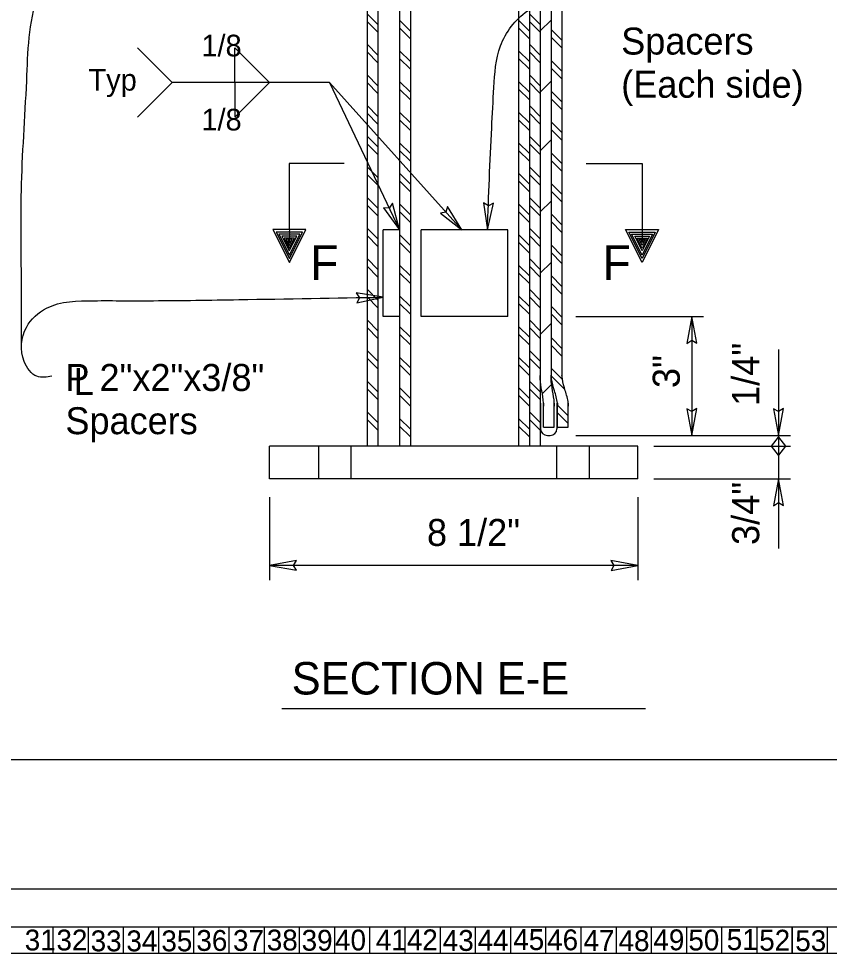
# Model space of a CAD drawing. Extents: x 0 to 2.83, y -0.03 to 1.83.
# Drawn here: x 0.6135 to 1.0034, y -0.0308 to 0.4189 of the extents above; entities that cross this region are included whole.
import ezdxf

# ---------------------------------------------------------------- set-up
doc = ezdxf.new("R2010")
doc.units = 0
for name, color, linetype in [('31', 7, 'Continuous'), ('32', 7, 'Continuous'), ('33', 7, 'Continuous'), ('34', 7, 'Continuous'), ('35', 7, 'Continuous'), ('36', 7, 'Continuous'), ('37', 7, 'Continuous'), ('38', 7, 'Continuous'), ('39', 7, 'Continuous'), ('40', 7, 'Continuous'), ('41', 7, 'Continuous'), ('42', 7, 'Continuous'), ('43', 7, 'Continuous'), ('44', 7, 'Continuous'), ('45', 7, 'Continuous'), ('46', 7, 'Continuous'), ('47', 7, 'Continuous'), ('48', 7, 'Continuous'), ('49', 7, 'Continuous'), ('50', 7, 'Continuous'), ('51', 7, 'Continuous'), ('52', 7, 'Continuous'), ('53', 7, 'Continuous'), ('54', 7, 'Continuous'), ('55', 7, 'Continuous'), ('57', 7, 'Continuous'), ('59', 7, 'Continuous'), ('62', 7, 'Continuous'), ('63', 7, 'Continuous')]:
    doc.layers.add(name, color=color, linetype=linetype)

msp = doc.modelspace()

# ---------------------------------------------------------------- linework, layer by layer
at = {"layer": '50'}
for p, q in [((0.86439, 0.41305), (0.8696, 0.41826)), ((0.86439, 0.38359), (0.8696, 0.3888)), ((0.86439, 0.35537), (0.8696, 0.36058)), ((0.86439, 0.32591), (0.8696, 0.33112)), ((0.86439, 0.29644), (0.8696, 0.30165)), ((0.86439, 0.26698), (0.8696, 0.27219)), ((0.86532, 0.23844), (0.86989, 0.24301))]:
    msp.add_line(p, q, dxfattribs=at)
at = {"layer": '52'}
for p, q in [((0.79669, 0.64876), (0.79669, 0.21316)), ((0.80189, 0.64876), (0.80189, 0.21316)), ((0.85398, 0.64876), (0.85398, 0.21316)), ((0.85919, 0.64876), (0.85919, 0.21316)), ((0.8696, 0.57644), (0.8696, 0.24567)), ((0.87481, 0.57644), (0.87481, 0.24743)), ((0.78106, 0.57253), (0.78106, 0.21316)), ((0.78627, 0.57253), (0.78627, 0.21316)), ((0.86439, 0.57253), (0.86439, 0.21316)), ((0.78627, 0.41611), (0.78106, 0.42132)), ((0.86439, 0.41611), (0.85919, 0.42132)), ((0.78627, 0.41243), (0.78106, 0.41763)), ((0.80189, 0.41297), (0.79669, 0.41818)), ((0.80189, 0.40928), (0.79669, 0.41449)), ((0.85919, 0.41297), (0.85398, 0.41818)), ((0.85919, 0.40928), (0.85398, 0.41449)), ((0.86439, 0.41243), (0.85919, 0.41763)), ((0.87481, 0.40853), (0.8696, 0.41373)), ((0.87481, 0.40484), (0.8696, 0.41005)), ((0.78627, 0.40138), (0.78106, 0.40659)), ((0.86439, 0.40138), (0.85919, 0.40659)), ((0.78627, 0.3977), (0.78106, 0.4029)), ((0.80189, 0.39824), (0.79669, 0.40344)), ((0.85919, 0.39824), (0.85398, 0.40344)), ((0.86439, 0.3977), (0.85919, 0.4029)), ((0.80189, 0.39455), (0.79669, 0.39976)), ((0.85919, 0.39455), (0.85398, 0.39976)), ((0.87481, 0.3936), (0.8696, 0.39881)), ((0.78627, 0.38665), (0.78106, 0.39185)), ((0.86439, 0.38665), (0.85919, 0.39185)), ((0.87481, 0.38992), (0.8696, 0.39512)), ((0.78627, 0.38296), (0.78106, 0.38817)), ((0.80189, 0.38351), (0.79669, 0.38871)), ((0.85919, 0.38351), (0.85398, 0.38871)), ((0.86439, 0.38296), (0.85919, 0.38817)), ((0.80189, 0.37982), (0.79669, 0.38503)), ((0.85919, 0.37982), (0.85398, 0.38503)), ((0.87481, 0.37887), (0.8696, 0.38408)), ((0.87481, 0.37519), (0.8696, 0.38039)), ((0.78627, 0.37192), (0.78106, 0.37712)), ((0.78627, 0.36823), (0.78106, 0.37344)), ((0.80189, 0.36877), (0.79669, 0.37398)), ((0.85919, 0.36877), (0.85398, 0.37398)), ((0.86439, 0.37192), (0.85919, 0.37712)), ((0.86439, 0.36823), (0.85919, 0.37344)), ((0.80189, 0.36509), (0.79669, 0.3703)), ((0.85919, 0.36509), (0.85398, 0.3703)), ((0.87481, 0.36414), (0.8696, 0.36934)), ((0.87481, 0.36045), (0.8696, 0.36566)), ((0.78627, 0.35718), (0.78106, 0.36239)), ((0.86439, 0.35718), (0.85919, 0.36239)), ((0.78627, 0.3535), (0.78106, 0.35871)), ((0.80189, 0.35404), (0.79669, 0.35925)), ((0.80189, 0.35036), (0.79669, 0.35557)), ((0.85919, 0.35404), (0.85398, 0.35925)), ((0.85919, 0.35036), (0.85398, 0.35557)), ((0.86439, 0.3535), (0.85919, 0.35871)), ((0.87481, 0.34921), (0.8696, 0.35442)), ((0.78627, 0.34245), (0.78106, 0.34766)), ((0.86439, 0.34245), (0.85919, 0.34766)), ((0.87481, 0.34553), (0.8696, 0.35074)), ((0.78627, 0.33877), (0.78106, 0.34398)), ((0.80189, 0.33931), (0.79669, 0.34452)), ((0.85919, 0.33931), (0.85398, 0.34452)), ((0.86439, 0.33877), (0.85919, 0.34398)), ((0.80189, 0.33563), (0.79669, 0.34084)), ((0.85919, 0.33563), (0.85398, 0.34084)), ((0.87481, 0.33448), (0.8696, 0.33969)), ((0.78627, 0.32772), (0.78106, 0.33293)), ((0.86439, 0.32772), (0.85919, 0.33293)), ((0.87481, 0.3308), (0.8696, 0.336)), ((0.78627, 0.32404), (0.78106, 0.32925)), ((0.80189, 0.32458), (0.79669, 0.32979)), ((0.85919, 0.32458), (0.85398, 0.32979)), ((0.86439, 0.32404), (0.85919, 0.32925)), ((0.80189, 0.3209), (0.79669, 0.3261)), ((0.85919, 0.3209), (0.85398, 0.3261)), ((0.87481, 0.31975), (0.8696, 0.32496)), ((0.87481, 0.31606), (0.8696, 0.32127)), ((0.78627, 0.31299), (0.78106, 0.3182)), ((0.79669, 0.31732), (0.78887, 0.31732)), ((0.78887, 0.27566), (0.78887, 0.31732)), ((0.80189, 0.30985), (0.79669, 0.31506)), ((0.8071, 0.27566), (0.8071, 0.31732)), ((0.84877, 0.31732), (0.8071, 0.31732)), ((0.84877, 0.27566), (0.84877, 0.31732)), ((0.85919, 0.30985), (0.85398, 0.31506)), ((0.86439, 0.31299), (0.85919, 0.3182)), ((0.78627, 0.30931), (0.78106, 0.31452)), ((0.80189, 0.30617), (0.79669, 0.31137)), ((0.85919, 0.30617), (0.85398, 0.31137)), ((0.86439, 0.30931), (0.85919, 0.31452)), ((0.87481, 0.30482), (0.8696, 0.31003)), ((0.87481, 0.30114), (0.8696, 0.30635)), ((0.78627, 0.29826), (0.78106, 0.30347)), ((0.86439, 0.29826), (0.85919, 0.30347)), ((0.78627, 0.29458), (0.78106, 0.29978)), ((0.80189, 0.29512), (0.79669, 0.30033)), ((0.85919, 0.29512), (0.85398, 0.30033)), ((0.86439, 0.29458), (0.85919, 0.29978)), ((0.80189, 0.29143), (0.79669, 0.29664)), ((0.85919, 0.29143), (0.85398, 0.29664)), ((0.87481, 0.29009), (0.8696, 0.2953)), ((0.78627, 0.28353), (0.78106, 0.28874)), ((0.86439, 0.28353), (0.85919, 0.28874)), ((0.87481, 0.28641), (0.8696, 0.29162)), ((0.78627, 0.27984), (0.78106, 0.28505)), ((0.80189, 0.28039), (0.79669, 0.28559)), ((0.85919, 0.28039), (0.85398, 0.28559)), ((0.86439, 0.27984), (0.85919, 0.28505)), ((0.80189, 0.2767), (0.79669, 0.28191)), ((0.85919, 0.2767), (0.85398, 0.28191)), ((0.87481, 0.27536), (0.8696, 0.28057)), ((0.79669, 0.27566), (0.78887, 0.27566)), ((0.84877, 0.27566), (0.8071, 0.27566)), ((0.87481, 0.27168), (0.8696, 0.27688)), ((0.78627, 0.2688), (0.78106, 0.274)), ((0.78627, 0.26511), (0.78106, 0.27032)), ((0.80189, 0.26565), (0.79669, 0.27086)), ((0.85919, 0.26565), (0.85398, 0.27086)), ((0.86439, 0.2688), (0.85919, 0.274)), ((0.86439, 0.26511), (0.85919, 0.27032)), ((0.80189, 0.26197), (0.79669, 0.26718)), ((0.85919, 0.26197), (0.85398, 0.26718)), ((0.87481, 0.26029), (0.8696, 0.26549)), ((0.87481, 0.2566), (0.8696, 0.26181)), ((0.78627, 0.25406), (0.78106, 0.25927)), ((0.86439, 0.25406), (0.85919, 0.25927)), ((0.78627, 0.25038), (0.78106, 0.25559)), ((0.80189, 0.25092), (0.79669, 0.25613)), ((0.80189, 0.24724), (0.79669, 0.25245)), ((0.85919, 0.25092), (0.85398, 0.25613)), ((0.85919, 0.24724), (0.85398, 0.25245)), ((0.86439, 0.25038), (0.85919, 0.25559)), ((0.87513, 0.24523), (0.8696, 0.25076)), ((0.78627, 0.23933), (0.78106, 0.24454)), ((0.86439, 0.23933), (0.85919, 0.24454)), ((0.87625, 0.24044), (0.86962, 0.24706)), ((0.78627, 0.23565), (0.78106, 0.24086)), ((0.80189, 0.23619), (0.79669, 0.2414)), ((0.85919, 0.23619), (0.85398, 0.2414)), ((0.86439, 0.23565), (0.85919, 0.24086)), ((0.80189, 0.23251), (0.79669, 0.23772)), ((0.85919, 0.23251), (0.85398, 0.23772)), ((0.86456, 0.23399), (0.86456, 0.22162)), ((0.86586, 0.22231), (0.86586, 0.23399)), ((0.86586, 0.23399), (0.86586, 0.23243)), ((0.87107, 0.22231), (0.87107, 0.23399)), ((0.87107, 0.23399), (0.87107, 0.23243)), ((0.87237, 0.23399), (0.87237, 0.22162)), ((0.87259, 0.22231), (0.87259, 0.23399)), ((0.87259, 0.23399), (0.87259, 0.23243)), ((0.8778, 0.22231), (0.8778, 0.23399)), ((0.8778, 0.23399), (0.8778, 0.23243)), ((0.78627, 0.2246), (0.78106, 0.22981)), ((0.86439, 0.2246), (0.85919, 0.22981)), ((0.8778, 0.22775), (0.87259, 0.23296)), ((0.78627, 0.22092), (0.78106, 0.22613)), ((0.80189, 0.22138), (0.79669, 0.22659)), ((0.85919, 0.22138), (0.85398, 0.22659)), ((0.86439, 0.22092), (0.85919, 0.22613)), ((0.8778, 0.22407), (0.87259, 0.22927)), ((0.80189, 0.21769), (0.79669, 0.2229)), ((0.85919, 0.21769), (0.85398, 0.2229)), ((0.86586, 0.22231), (0.87107, 0.22231)), ((0.87259, 0.22231), (0.8778, 0.22231)), ((0.86782, 0.21836), (0.86912, 0.21836)), ((0.91127, 0.21316), (0.73419, 0.21316)), ((0.73419, 0.19753), (0.73419, 0.21316)), ((0.75761, 0.21316), (0.75761, 0.19753)), ((0.77324, 0.21316), (0.77324, 0.19753)), ((0.87219, 0.21316), (0.87219, 0.19753)), ((0.88782, 0.21316), (0.88782, 0.19753)), ((0.91127, 0.19753), (0.91127, 0.21316)), ((0.91127, 0.19753), (0.73419, 0.19753))]:
    msp.add_line(p, q, dxfattribs=at)
for centre, start, end in [((0.86782, 0.22162), 180, 270), ((0.86912, 0.22162), 270, 0)]:
    msp.add_arc(centre, 0.00326, start, end, dxfattribs=at)
for points in [[(0.87259, 0.23243), (0.87259, 0.23399), (0.87116, 0.23993), (0.86982, 0.24567), (0.8696, 0.24743)], [(0.8778, 0.23243), (0.8778, 0.23399), (0.87637, 0.23993), (0.87503, 0.24567), (0.87481, 0.24743)], [(0.86586, 0.23243), (0.86586, 0.23399), (0.86513, 0.23983), (0.86439, 0.24567), (0.86439, 0.24727)], [(0.87107, 0.23243), (0.87107, 0.23399), (0.87034, 0.23983), (0.8696, 0.24567), (0.8696, 0.24727)]]:
    msp.add_spline(points, degree=3, dxfattribs=at)
at = {"layer": '54'}
msp.add_line((0.97898, 0.21316), (0.97898, 0.21316), dxfattribs=at)
for points in [[(0.83891, 0.31732), (0.84184, 0.3302), (0.8394, 0.3288), (0.83706, 0.33026)], [(0.78887, 0.28491), (0.77584, 0.28703), (0.77739, 0.28468), (0.77608, 0.28226)], [(0.93731, 0.27566), (0.93494, 0.26266), (0.93731, 0.26417), (0.93971, 0.26281)], [(0.93731, 0.21836), (0.93969, 0.23136), (0.93731, 0.22985), (0.93491, 0.23121)], [(0.97898, 0.21836), (0.98135, 0.23136), (0.97898, 0.22985), (0.97658, 0.23121)], [(0.97898, 0.20882), (0.97565, 0.21316), (0.97898, 0.21749), (0.9823, 0.21316)], [(0.97898, 0.19753), (0.9766, 0.18454), (0.97898, 0.18605), (0.98138, 0.18469)], [(0.73419, 0.15586), (0.74718, 0.15349), (0.74567, 0.15586), (0.74703, 0.15826)], [(0.91127, 0.15586), (0.89828, 0.15824), (0.89979, 0.15586), (0.89843, 0.15346)]]:
    msp.add_lwpolyline(points, close=True, dxfattribs=at)
at = {"layer": '55'}
for p, q in [((0.88155, 0.27566), (0.9429, 0.27566)), ((0.93731, 0.27566), (0.93731, 0.21836)), ((0.97898, 0.2598), (0.97898, 0.21836)), ((0.88155, 0.21836), (0.98482, 0.21836)), ((0.97898, 0.21836), (0.97898, 0.21316)), ((0.91898, 0.21316), (0.98482, 0.21316)), ((0.97898, 0.21316), (0.97898, 0.19753)), ((0.91898, 0.19753), (0.98482, 0.19753)), ((0.97898, 0.19753), (0.97898, 0.16398)), ((0.73419, 0.18872), (0.73419, 0.14868)), ((0.91127, 0.18872), (0.91127, 0.14868)), ((0.91127, 0.15586), (0.73419, 0.15586))]:
    msp.add_line(p, q, dxfattribs=at)
for points in [[(0.76999, 0.34917), (0.74358, 0.34917), (0.74358, 0.31742), (0.73573, 0.31742), (0.74366, 0.30154), (0.7516, 0.31742), (0.74369, 0.31742), (0.74358, 0.31624), (0.73734, 0.31624), (0.74369, 0.30354), (0.75004, 0.31624), (0.74369, 0.31624), (0.74358, 0.31529), (0.73862, 0.31529), (0.7437, 0.30513), (0.74878, 0.31529), (0.74369, 0.31529), (0.74358, 0.31434), (0.74006, 0.31434), (0.74364, 0.30719), (0.74721, 0.31434), (0.74369, 0.31434), (0.74358, 0.31334), (0.7411, 0.31334), (0.74364, 0.30831), (0.74614, 0.31334), (0.74369, 0.31334), (0.74358, 0.31277), (0.74215, 0.31277), (0.74362, 0.30984), (0.74508, 0.31277), (0.74369, 0.31277), (0.74358, 0.3122), (0.74304, 0.3122), (0.74358, 0.31111), (0.74413, 0.3122), (0.74369, 0.3122)], [(0.88638, 0.34917), (0.91344, 0.34917), (0.91344, 0.31742), (0.92129, 0.31742), (0.91336, 0.30154), (0.90542, 0.31742), (0.91332, 0.31742), (0.91344, 0.31624), (0.91968, 0.31624), (0.91333, 0.30354), (0.90698, 0.31624), (0.91332, 0.31624), (0.91344, 0.31529), (0.9184, 0.31529), (0.91332, 0.30513), (0.90824, 0.31529), (0.91332, 0.31529), (0.91344, 0.31434), (0.91696, 0.31434), (0.91337, 0.30719), (0.90981, 0.31434), (0.91332, 0.31434), (0.91344, 0.31334), (0.91592, 0.31334), (0.91338, 0.30831), (0.91087, 0.31334), (0.91332, 0.31334), (0.91344, 0.31277), (0.91487, 0.31277), (0.9134, 0.30984), (0.91194, 0.31277), (0.91332, 0.31277), (0.91344, 0.3122), (0.91397, 0.3122), (0.91344, 0.31111), (0.91289, 0.3122), (0.91332, 0.3122)]]:
    msp.add_lwpolyline(points, dxfattribs=at)
for points in [[(0.78887, 0.48021), (0.70479, 0.47739), (0.64937, 0.46465), (0.62261, 0.43025), (0.61713, 0.38899), (0.61457, 0.33611), (0.61457, 0.29812), (0.61463, 0.26115)], [(0.83891, 0.31732), (0.84102, 0.36647), (0.84207, 0.38578), (0.84523, 0.40579), (0.85822, 0.42265), (0.87332, 0.42855), (0.88916, 0.42862), (0.89439, 0.42862)], [(0.62946, 0.24683), (0.62224, 0.24683), (0.61611, 0.25397), (0.61713, 0.2704), (0.62689, 0.27964), (0.64948, 0.28323), (0.67823, 0.28323), (0.7193, 0.28374), (0.78887, 0.28491)]]:
    msp.add_spline(points, degree=3, dxfattribs=at)
at = {"layer": '57'}
msp.add_line((0.74005, 0.08699), (0.91495, 0.08699), dxfattribs=at)
at = {"layer": '59'}
for p, q in [((0.76301, 0.38819), (0.68721, 0.38819)), ((0.68721, 0.38819), (0.68721, 0.38819)), ((0.7258, 0.38819), (0.7258, 0.38819)), ((0.7258, 0.38819), (0.7258, 0.38819)), ((0.76301, 0.38819), (0.82668, 0.31732)), ((0.76301, 0.38819), (0.79669, 0.31732))]:
    msp.add_line(p, q, dxfattribs=at)
for points in [[(0.67054, 0.40485), (0.68721, 0.38819), (0.67054, 0.37152)], [(0.71747, 0.38819), (0.71747, 0.40485), (0.73413, 0.38819)], [(0.71747, 0.38819), (0.71747, 0.37152), (0.73413, 0.38819)]]:
    msp.add_lwpolyline(points, dxfattribs=at)
for points in [[(0.79669, 0.31732), (0.79325, 0.33008), (0.79176, 0.3277), (0.78901, 0.32789)], [(0.82668, 0.31732), (0.81976, 0.32857), (0.819, 0.32587), (0.81631, 0.32527)]]:
    msp.add_lwpolyline(points, close=True, dxfattribs=at)
at = {"layer": '62'}
for p, q in [((0.10494, -0.01804), (1.17174, -0.01804)), ((0.10496, -0.0181), (1.17175, -0.0181)), ((0.62988, -0.01804), (0.62988, -0.03074)), ((0.62989, -0.0181), (0.62989, -0.0308)), ((0.64681, -0.01804), (0.64681, -0.03074)), ((0.64682, -0.0181), (0.64682, -0.0308)), ((0.66374, -0.01804), (0.66374, -0.03074)), ((0.66376, -0.0181), (0.66376, -0.0308)), ((0.68068, -0.01804), (0.68068, -0.03074)), ((0.68069, -0.0181), (0.68069, -0.0308)), ((0.69761, -0.01804), (0.69761, -0.03074)), ((0.69762, -0.0181), (0.69762, -0.0308)), ((0.71454, -0.01804), (0.71454, -0.03074)), ((0.71456, -0.0181), (0.71456, -0.0308)), ((0.73147, -0.01804), (0.73147, -0.03074)), ((0.73149, -0.0181), (0.73149, -0.0308)), ((0.74841, -0.01804), (0.74841, -0.03074)), ((0.74842, -0.0181), (0.74842, -0.0308)), ((0.76534, -0.01804), (0.76534, -0.03074)), ((0.76536, -0.0181), (0.76536, -0.0308)), ((0.78228, -0.01804), (0.78228, -0.03074)), ((0.78229, -0.0181), (0.78229, -0.0308)), ((0.79921, -0.01804), (0.79921, -0.03074)), ((0.79922, -0.0181), (0.79922, -0.0308)), ((0.81614, -0.01804), (0.81614, -0.03074)), ((0.81616, -0.0181), (0.81616, -0.0308)), ((0.83308, -0.01804), (0.83308, -0.03074)), ((0.83309, -0.0181), (0.83309, -0.0308)), ((0.85001, -0.01804), (0.85001, -0.03074)), ((0.85002, -0.0181), (0.85002, -0.0308)), ((0.86694, -0.01804), (0.86694, -0.03074)), ((0.86695, -0.0181), (0.86695, -0.0308)), ((0.88388, -0.01804), (0.88388, -0.03074)), ((0.88389, -0.0181), (0.88389, -0.0308)), ((0.90081, -0.01804), (0.90081, -0.03074)), ((0.90082, -0.0181), (0.90082, -0.0308)), ((0.91774, -0.01804), (0.91774, -0.03074)), ((0.91775, -0.0181), (0.91775, -0.0308)), ((0.93468, -0.01804), (0.93468, -0.03074)), ((0.93469, -0.0181), (0.93469, -0.0308)), ((0.95161, -0.01804), (0.95161, -0.03074)), ((0.95162, -0.0181), (0.95162, -0.0308)), ((0.96854, -0.01804), (0.96854, -0.03074)), ((0.96855, -0.0181), (0.96855, -0.0308)), ((0.98548, -0.01804), (0.98548, -0.03074)), ((0.98549, -0.0181), (0.98549, -0.0308)), ((1.00241, -0.01804), (1.00241, -0.03074)), ((1.00242, -0.0181), (1.00242, -0.0308)), ((0.10494, -0.03074), (1.17174, -0.03074)), ((0.10496, -0.0308), (1.17175, -0.0308))]:
    msp.add_line(p, q, dxfattribs=at)
at = {"layer": '63'}
msp.add_line((2.83333, 0), (0, 0), dxfattribs=at)
msp.add_lwpolyline([(2.72918, 1.77077), (0.10418, 1.77077), (0.10418, 0.06244), (2.72918, 0.06244)], close=True, dxfattribs=at)

# ---------------------------------------------------------------- texts
at = {"layer": '31'}
for p in [(0.61636, -0.02938), (0.61637, -0.02943)]:
    msp.add_text('31', height=0.01, rotation=360, dxfattribs=at).set_placement(p)
at = {"layer": '32'}
for p in [(0.63163, -0.02938), (0.63165, -0.02943)]:
    msp.add_text('32', height=0.01, rotation=360, dxfattribs=at).set_placement(p)
at = {"layer": '33'}
for p in [(0.64808, -0.02978), (0.64809, -0.02983)]:
    msp.add_text('33', height=0.01, rotation=360, dxfattribs=at).set_placement(p)
at = {"layer": '34'}
for p in [(0.66527, -0.02978), (0.66528, -0.02984)]:
    msp.add_text('34', height=0.01, rotation=360, dxfattribs=at).set_placement(p)
at = {"layer": '35'}
for p in [(0.68209, -0.02978), (0.68211, -0.02984)]:
    msp.add_text('35', height=0.01, rotation=360, dxfattribs=at).set_placement(p)
at = {"layer": '36'}
for p in [(0.69895, -0.02958), (0.69896, -0.02964)]:
    msp.add_text('36', height=0.01, rotation=360, dxfattribs=at).set_placement(p)
at = {"layer": '37'}
for p in [(0.71654, -0.02958), (0.71655, -0.02964)]:
    msp.add_text('37', height=0.01, rotation=360, dxfattribs=at).set_placement(p)
at = {"layer": '38'}
for p in [(0.73281, -0.02938), (0.73282, -0.02943)]:
    msp.add_text('38', height=0.01, rotation=360, dxfattribs=at).set_placement(p)
at = {"layer": '39'}
for p in [(0.74958, -0.0295), (0.74959, -0.02955)]:
    msp.add_text('39', height=0.01, rotation=360, dxfattribs=at).set_placement(p)
at = {"layer": '40'}
for p in [(0.76566, -0.02938), (0.76567, -0.02944)]:
    msp.add_text('40', height=0.01, rotation=360, dxfattribs=at).set_placement(p)
at = {"layer": '41'}
for p in [(0.78528, -0.02938), (0.7853, -0.02943)]:
    msp.add_text('41', height=0.01, rotation=360, dxfattribs=at).set_placement(p)
at = {"layer": '42'}
for p in [(0.8002, -0.0293), (0.80022, -0.02936)]:
    msp.add_text('42', height=0.01, rotation=360, dxfattribs=at).set_placement(p)
at = {"layer": '43'}
for p in [(0.8175, -0.02958), (0.81751, -0.02964)]:
    msp.add_text('43', height=0.01, rotation=360, dxfattribs=at).set_placement(p)
at = {"layer": '44'}
for p in [(0.83425, -0.02949), (0.83427, -0.02955)]:
    msp.add_text('44', height=0.01, rotation=360, dxfattribs=at).set_placement(p)
at = {"layer": '45'}
for p in [(0.85139, -0.02918), (0.8514, -0.02924)]:
    msp.add_text('45', height=0.01, rotation=360, dxfattribs=at).set_placement(p)
at = {"layer": '46'}
for p in [(0.8677, -0.02929), (0.86771, -0.02935)]:
    msp.add_text('46', height=0.01, rotation=360, dxfattribs=at).set_placement(p)
at = {"layer": '47'}
for p in [(0.8852, -0.02958), (0.88522, -0.02964)]:
    msp.add_text('47', height=0.01, rotation=360, dxfattribs=at).set_placement(p)
at = {"layer": '48'}
for p in [(0.90205, -0.02969), (0.90206, -0.02975)]:
    msp.add_text('48', height=0.01, rotation=360, dxfattribs=at).set_placement(p)
at = {"layer": '49'}
for p in [(0.91882, -0.02929), (0.91883, -0.02935)]:
    msp.add_text('49', height=0.01, rotation=360, dxfattribs=at).set_placement(p)
at = {"layer": '50'}
for p in [(0.93563, -0.02938), (0.93564, -0.02944)]:
    msp.add_text('50', height=0.01, rotation=360, dxfattribs=at).set_placement(p)
at = {"layer": '51'}
for p in [(0.95407, -0.02918), (0.95408, -0.02923)]:
    msp.add_text('51', height=0.01, rotation=360, dxfattribs=at).set_placement(p)
at = {"layer": '52'}
for p in [(0.96972, -0.02946), (0.96973, -0.02952)]:
    msp.add_text('52', height=0.01, rotation=360, dxfattribs=at).set_placement(p)
at = {"layer": '53'}
for p in [(0.98705, -0.0297), (0.98707, -0.02976)]:
    msp.add_text('53', height=0.01, rotation=360, dxfattribs=at).set_placement(p)
at = {"layer": '57'}
for s, height, p in [('Spacers', 0.01298, (0.90331, 0.40166)), ('1/8', 0.010417, (0.70135, 0.40078)), ('Typ', 0.010417, (0.64704, 0.3843)), ('(Each side)', 0.0129801, (0.90331, 0.38087)), ('1/8', 0.010417, (0.70135, 0.36514)), ('F', 0.01667, (0.7537, 0.29321)), ('F', 0.01667, (0.89431, 0.29321)), ('P 2"x2"x3/8"', 0.0129801, (0.63593, 0.23979)), ('L', 0.01298, (0.63991, 0.23779)), ('Spacers', 0.01298, (0.63593, 0.21899)), ('8 1/2"', 0.01298, (0.80988, 0.16522)), ('SECTION E-E', 0.015625, (0.74478, 0.09374))]:
    msp.add_text(s, height=height, dxfattribs=at).set_placement(p)
for s, p in [('1/4"', (0.9697, 0.23259)), ('3"', (0.93149, 0.24119)), ('3/4"', (0.9697, 0.16567))]:
    msp.add_text(s, height=0.013021, rotation=90, dxfattribs=at).set_placement(p)

doc.saveas('drawing.dxf')
